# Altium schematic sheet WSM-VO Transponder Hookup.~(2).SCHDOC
size B; Organization: Monterey Bay Aquarium Research Institute; Address1: 7700 Sandholdt Rd; Address2: Moss Landing, CA 95039-9644; CompanyName: MBARI; PageSetup: Record=PageOptions|CenterHorizontal=True|CenterVertical=True|PrintScale=0.70|XCorrection=1.00|YCorrection=1.00|PrintKind=0|BorderSize=5000000|LeftOffset=0|BottomOffset=0|Orientation=2|PaperLength=1000|PaperWidth=1000|Scale=100|PaperSource=7|PrintQuality=-4|MediaType=1|DitherType=10|PaperKind=Letter|PrintScaleMode=1
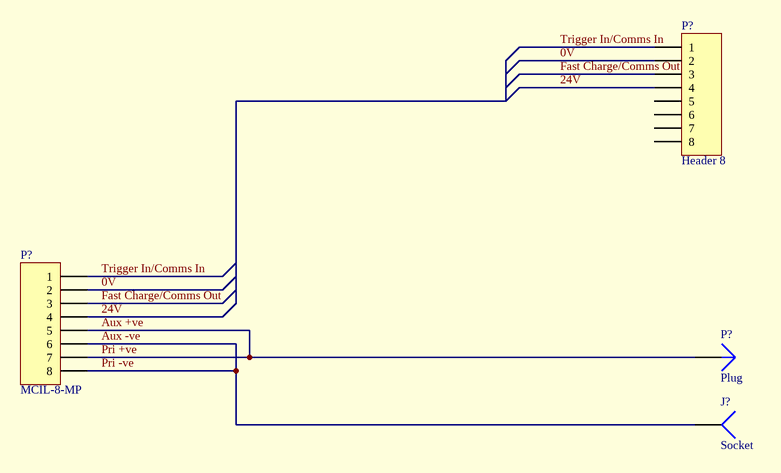
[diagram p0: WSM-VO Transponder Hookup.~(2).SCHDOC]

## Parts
(Parts that share a designator on the sheet are numbered #1, #2 ... from top to bottom, then left to right.)
J?  Socket  [PIN1]
P?#1  Header 8  [HDR1X8]
P?#2  MCIL-8-MP  [HDR1X8]
P?#3  Plug  [PIN1]

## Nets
0V: P?#1.2 P?#2.2
24V: P?#1.4 P?#2.4
Aux +ve: P?#2.5 P?#2.7 P?#3.1  [also labelled Pri +ve]
Aux -ve: J?.1 P?#2.6 P?#2.8  [also labelled Pri -ve]
Fast Charge/Comms Out: P?#1.3 P?#2.3
Trigger In/Comms In: P?#1.1 P?#2.1

Not connected (* = marked no-connect by the designer): P?#1 5 6 7 8

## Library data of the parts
P?#1 P?#2 = Header 8: Header, 8-Pin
